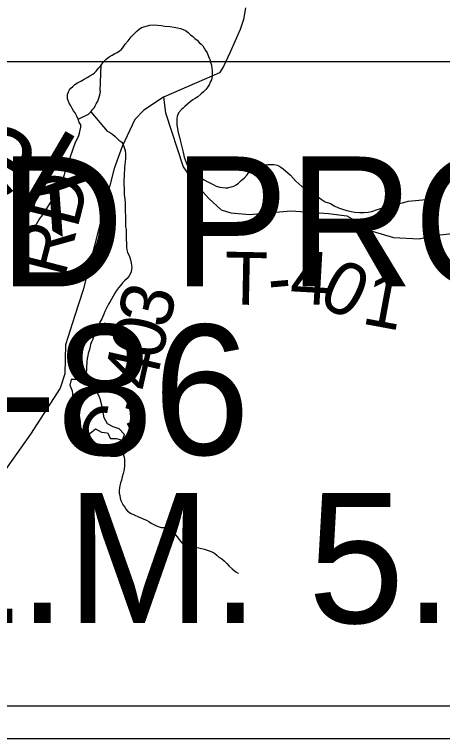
# Model space of a CAD drawing. Extents: x -59 to 82, y -3 to 49.
# Drawn here: x -51.129 to -50.668, y 42.491 to 43.271 of the extents above; entities that cross this region are included whole.
import ezdxf

# ---------------------------------------------------------------- set-up
doc = ezdxf.new("R2010")
doc.units = 0
for name, color, linetype in [('GM_X_Corporation', 7, 'Continuous'), ('GM_X_County_Road', 7, 'Continuous'), ('GM_X_County_Road_Text', 7, 'Continuous'), ('GM_X_Minor_Lake', 7, 'Continuous'), ('GM_X_Minor_River', 7, 'Continuous'), ('GM_X_Minor_River_Text', 7, 'Continuous'), ('GM_X_Township_Road', 7, 'Continuous'), ('GM_X_Township_Road_Text', 7, 'Continuous'), ('SH_Data', 7, 'Continuous')]:
    doc.layers.add(name, color=color, linetype=linetype)

msp = doc.modelspace()

# ---------------------------------------------------------------- linework, layer by layer
at = {"layer": 'GM_X_Corporation'}
for q in [(-48.09799, 42.49125), (-49.94786, 42.49125)]:
    msp.add_line((-54.89799, 42.49125), q, dxfattribs=at)
at = {"layer": 'GM_X_County_Road'}
for p, q in [((-50.88002, 43.27801), (-50.88211, 43.26547)), ((-50.88211, 43.26547), (-50.88559, 43.25479)), ((-50.88559, 43.25479), (-50.89627, 43.23017)), ((-50.89627, 43.23017), (-50.90346, 43.21485)), ((-50.90806, 43.20822), (-50.93272, 43.19743)), ((-50.90346, 43.21485), (-50.90806, 43.20822)), ((-50.93272, 43.19743), (-50.96824, 43.18176)), ((-50.96824, 43.18176), (-50.98953, 43.16783)), ((-50.98953, 43.16783), (-50.99899, 43.15765)), ((-50.99899, 43.15765), (-51.01281, 43.1289)), ((-51.01281, 43.1289), (-51.02123, 43.10517)), ((-51.02123, 43.10517), (-51.05474, 42.97432)), ((-51.05474, 42.97432), (-51.06363, 42.94692)), ((-51.06363, 42.94692), (-51.07363, 42.91533)), ((-51.07363, 42.91533), (-51.07453, 42.88382)), ((-51.07453, 42.88382), (-51.07935, 42.86859)), ((-51.07935, 42.86859), (-51.11156, 42.81901)), ((-51.11156, 42.81901), (-51.34477, 42.49125))]:
    msp.add_line(p, q, dxfattribs=at)
at = {"layer": 'GM_X_Minor_Lake'}
for p, q in [((-51.06764, 42.87779), (-51.06897, 42.87172)), ((-51.04694, 42.87782), (-51.06764, 42.87779)), ((-51.04247, 42.87024), (-51.04694, 42.87782)), ((-51.06897, 42.87172), (-51.06669, 42.86565)), ((-51.06669, 42.86565), (-51.06592, 42.85883)), ((-51.03987, 42.86534), (-51.04247, 42.87024)), ((-51.03639, 42.85698), (-51.03987, 42.86534)), ((-51.06592, 42.85883), (-51.06704, 42.852)), ((-51.06704, 42.852), (-51.06513, 42.84517)), ((-51.03448, 42.85015), (-51.03639, 42.85698)), ((-51.03218, 42.8365), (-51.03448, 42.85015)), ((-51.06513, 42.84517), (-51.05906, 42.83911)), ((-51.05906, 42.83911), (-51.05791, 42.83267)), ((-51.02838, 42.83006), (-51.03218, 42.8365)), ((-51.05791, 42.83267), (-51.05752, 42.82622)), ((-51.05752, 42.82622), (-51.0541, 42.82016)), ((-51.02232, 42.82704), (-51.02838, 42.83006)), ((-51.01588, 42.82477), (-51.02232, 42.82704)), ((-51.0541, 42.82016), (-51.04766, 42.81979)), ((-51.04766, 42.81979), (-51.04162, 42.82473)), ((-51.04162, 42.82473), (-51.03518, 42.82095)), ((-51.03518, 42.82095), (-51.02836, 42.82058)), ((-51.02836, 42.82058), (-51.02532, 42.81413)), ((-51.01018, 42.81871), (-51.01588, 42.82477)), ((-51.01244, 42.81264), (-51.01018, 42.81871)), ((-51.02532, 42.81413), (-51.01926, 42.81415)), ((-51.01926, 42.81415), (-51.01244, 42.81264))]:
    msp.add_line(p, q, dxfattribs=at)
at = {"layer": 'GM_X_Minor_River'}
for p, q in [((-50.99703, 43.25287), (-50.99439, 43.25517)), ((-50.99439, 43.25517), (-50.99175, 43.25671)), ((-50.99175, 43.25671), (-50.98304, 43.25944)), ((-50.98304, 43.25944), (-50.97886, 43.25985)), ((-50.97886, 43.25985), (-50.97468, 43.25949)), ((-50.97468, 43.25949), (-50.97088, 43.25914)), ((-50.97088, 43.25914), (-50.9667, 43.25841)), ((-50.9667, 43.25841), (-50.96138, 43.25807)), ((-50.96138, 43.25807), (-50.95682, 43.25734)), ((-50.95682, 43.25734), (-50.95301, 43.25661)), ((-50.95301, 43.25661), (-50.94997, 43.25587)), ((-50.94997, 43.25587), (-50.94692, 43.25475)), ((-51.00306, 43.24675), (-51.00004, 43.24981)), ((-51.00004, 43.24981), (-50.99703, 43.25287)), ((-50.94692, 43.25475), (-50.94464, 43.25362)), ((-50.94464, 43.25362), (-50.94158, 43.25136)), ((-50.94158, 43.25136), (-50.93928, 43.2491)), ((-50.93928, 43.2491), (-50.93661, 43.24722)), ((-50.93661, 43.24722), (-50.93431, 43.24495)), ((-51.00945, 43.23909), (-51.00644, 43.24254)), ((-51.00644, 43.24254), (-51.00306, 43.24675)), ((-50.93431, 43.24495), (-50.93202, 43.24307)), ((-50.93202, 43.24307), (-50.92972, 43.2408)), ((-50.92972, 43.2408), (-50.92781, 43.23891)), ((-51.01811, 43.22991), (-51.01547, 43.23183)), ((-51.01547, 43.23183), (-51.01358, 43.23336)), ((-51.01358, 43.23336), (-51.0117, 43.23566)), ((-51.0117, 43.23566), (-51.00945, 43.23909)), ((-50.92781, 43.23891), (-50.9259, 43.23702)), ((-50.9259, 43.23702), (-50.92436, 43.23475)), ((-50.92436, 43.23475), (-50.92282, 43.2321)), ((-50.92282, 43.2321), (-50.92128, 43.22945)), ((-51.02982, 43.2226), (-51.02681, 43.22528)), ((-51.02681, 43.22528), (-51.0234, 43.22721)), ((-51.0234, 43.22721), (-51.02076, 43.22875)), ((-51.02076, 43.22875), (-51.01811, 43.22991)), ((-50.92128, 43.22945), (-50.91973, 43.22566)), ((-50.91973, 43.22566), (-50.91818, 43.22225)), ((-51.0381, 43.21303), (-51.03547, 43.21647)), ((-51.03638, 43.18871), (-51.03547, 43.21647)), ((-51.03547, 43.21647), (-51.03284, 43.21992)), ((-51.03284, 43.21992), (-51.02982, 43.2226)), ((-50.91818, 43.22225), (-50.91739, 43.21845)), ((-50.91739, 43.21845), (-50.91661, 43.21617)), ((-50.91661, 43.21617), (-50.91621, 43.21276)), ((-51.04261, 43.20806), (-51.04073, 43.20997)), ((-51.04073, 43.20997), (-51.0381, 43.21303)), ((-50.91621, 43.21276), (-50.91581, 43.21048)), ((-50.91581, 43.21048), (-50.91579, 43.20743)), ((-51.05735, 43.19921), (-51.05357, 43.20113)), ((-51.05357, 43.20113), (-51.05055, 43.20306)), ((-51.05055, 43.20306), (-51.04753, 43.20498)), ((-51.04753, 43.20498), (-51.0445, 43.20652)), ((-51.0445, 43.20652), (-51.04261, 43.20806)), ((-50.91649, 43.20059), (-50.91761, 43.19868)), ((-50.91612, 43.20249), (-50.91649, 43.20059)), ((-50.91576, 43.20477), (-50.91612, 43.20249)), ((-50.91579, 43.20743), (-50.91576, 43.20477)), ((-51.06792, 43.19153), (-51.06604, 43.19344)), ((-51.06604, 43.19344), (-51.06378, 43.19536)), ((-51.06378, 43.19536), (-51.06075, 43.19728)), ((-51.06075, 43.19728), (-51.05735, 43.19921)), ((-50.9206, 43.19295), (-50.92248, 43.19027)), ((-50.9191, 43.19524), (-50.9206, 43.19295)), ((-50.91761, 43.19868), (-50.9191, 43.19524)), ((-51.07166, 43.18389), (-51.07129, 43.1858)), ((-51.07129, 43.1858), (-51.07055, 43.1877)), ((-51.07055, 43.1877), (-51.06943, 43.18961)), ((-51.06943, 43.18961), (-51.06792, 43.19153)), ((-51.0371, 43.18338), (-51.03636, 43.18567)), ((-51.036, 43.18833), (-51.03638, 43.18871)), ((-51.03636, 43.18567), (-51.036, 43.18833)), ((-50.92813, 43.18491), (-50.93115, 43.18223)), ((-50.92512, 43.18759), (-50.92813, 43.18491)), ((-50.92248, 43.19027), (-50.92512, 43.18759)), ((-51.07163, 43.18009), (-51.07166, 43.18389)), ((-51.07085, 43.1782), (-51.07163, 43.18009)), ((-51.06969, 43.17554), (-51.07085, 43.1782)), ((-51.04083, 43.17461), (-51.03895, 43.17766)), ((-51.03895, 43.17766), (-51.03784, 43.18071)), ((-51.03784, 43.18071), (-51.0371, 43.18338)), ((-50.93644, 43.17915), (-50.93946, 43.17684)), ((-50.93417, 43.18031), (-50.93644, 43.17915)), ((-50.93115, 43.18223), (-50.93417, 43.18031)), ((-51.06815, 43.17251), (-51.06969, 43.17554)), ((-51.06661, 43.16948), (-51.06815, 43.17251)), ((-51.06507, 43.16721), (-51.06661, 43.16948)), ((-51.0442, 43.16888), (-51.04269, 43.17079)), ((-51.04269, 43.17079), (-51.04195, 43.1727)), ((-51.04195, 43.1727), (-51.04083, 43.17461)), ((-50.947, 43.16995), (-50.94888, 43.16841)), ((-50.94511, 43.17186), (-50.947, 43.16995)), ((-50.94247, 43.17416), (-50.94511, 43.17186)), ((-50.93946, 43.17684), (-50.94247, 43.17416)), ((-51.06353, 43.16494), (-51.06507, 43.16721)), ((-51.0616, 43.16153), (-51.06353, 43.16494)), ((-51.06006, 43.15812), (-51.0616, 43.16153)), ((-51.06006, 43.15812), (-51.04909, 43.16352)), ((-51.04909, 43.16352), (-51.04645, 43.1662)), ((-51.04645, 43.1662), (-51.0442, 43.16888)), ((-51.04645, 43.1662), (-51.02882, 43.14541)), ((-50.95189, 43.16497), (-50.95338, 43.16116)), ((-50.94888, 43.16841), (-50.95189, 43.16497)), ((-51.05889, 43.1547), (-51.06006, 43.15812)), ((-51.05735, 43.15205), (-51.05889, 43.1547)), ((-50.95338, 43.16116), (-50.95374, 43.15887)), ((-50.95374, 43.15887), (-50.95372, 43.15583)), ((-50.95372, 43.15583), (-50.95368, 43.15165)), ((-51.05843, 43.14482), (-51.05733, 43.14939)), ((-51.05733, 43.14939), (-51.05735, 43.15205)), ((-50.95368, 43.15165), (-50.95328, 43.14823)), ((-50.95328, 43.14823), (-50.95288, 43.14557)), ((-51.06178, 43.13567), (-51.06065, 43.13796)), ((-51.06065, 43.13796), (-51.05954, 43.14063)), ((-51.05954, 43.14063), (-51.0588, 43.14292)), ((-51.0588, 43.14292), (-51.05843, 43.14482)), ((-51.02882, 43.14541), (-51.02653, 43.14428)), ((-51.02653, 43.14428), (-51.0231, 43.14203)), ((-51.0231, 43.14203), (-51.02042, 43.13939)), ((-51.02042, 43.13939), (-51.01851, 43.13788)), ((-50.95288, 43.14557), (-50.95209, 43.14253)), ((-50.95209, 43.14253), (-50.95092, 43.13874)), ((-50.95092, 43.13874), (-50.94975, 43.13418)), ((-51.06475, 43.12842), (-51.06327, 43.13224)), ((-51.06327, 43.13224), (-51.06178, 43.13567)), ((-51.01851, 43.13788), (-51.01621, 43.13561)), ((-51.01621, 43.13561), (-51.01315, 43.13335)), ((-51.01315, 43.13335), (-51.012, 43.13146)), ((-51.012, 43.13146), (-51.01084, 43.12881)), ((-50.94975, 43.13418), (-50.94856, 43.12849)), ((-51.06809, 43.11889), (-51.06624, 43.12423)), ((-51.06624, 43.12423), (-51.06475, 43.12842)), ((-51.01084, 43.12881), (-51.01006, 43.12653)), ((-51.01006, 43.12653), (-51.00966, 43.12425)), ((-51.00966, 43.12425), (-51.00925, 43.12083)), ((-50.94856, 43.12849), (-50.947, 43.1228)), ((-50.947, 43.1228), (-50.94581, 43.1171)), ((-51.06957, 43.11356), (-51.06809, 43.11889)), ((-51.00921, 43.11551), (-51.00957, 43.11246)), ((-51.00925, 43.12083), (-51.00923, 43.11817)), ((-51.00923, 43.11817), (-51.00921, 43.11551)), ((-50.94581, 43.1171), (-50.94426, 43.11255)), ((-51.07366, 43.10212), (-51.07143, 43.10822)), ((-51.07143, 43.10822), (-51.06957, 43.11356)), ((-51.00992, 43.10904), (-51.01027, 43.10599)), ((-51.00957, 43.11246), (-51.00992, 43.10904)), ((-50.94426, 43.11255), (-50.94271, 43.10876)), ((-50.94271, 43.10876), (-50.94116, 43.10573)), ((-50.86864, 43.10548), (-50.86447, 43.10703)), ((-50.86447, 43.10703), (-50.85993, 43.10858)), ((-50.85993, 43.10858), (-50.85576, 43.10937)), ((-50.85576, 43.10937), (-50.85196, 43.1094)), ((-50.85196, 43.1094), (-50.84892, 43.10942)), ((-50.84892, 43.10942), (-50.84588, 43.10868)), ((-50.84588, 43.10868), (-50.84397, 43.10794)), ((-50.84397, 43.10794), (-50.84168, 43.10643)), ((-51.07551, 43.0964), (-51.07366, 43.10212)), ((-51.01025, 43.10333), (-51.01061, 43.10029)), ((-51.01061, 43.10029), (-51.01058, 43.09649)), ((-51.01027, 43.10599), (-51.01025, 43.10333)), ((-50.94116, 43.10573), (-50.93849, 43.10346)), ((-50.93849, 43.10346), (-50.93619, 43.10158)), ((-50.93619, 43.10158), (-50.93313, 43.09894)), ((-50.87807, 43.09819), (-50.87469, 43.10277)), ((-50.87469, 43.10277), (-50.86864, 43.10548)), ((-50.84168, 43.10643), (-50.83939, 43.10455)), ((-50.83939, 43.10455), (-50.83136, 43.09776)), ((-51.08112, 43.08572), (-51.07775, 43.09145)), ((-51.07775, 43.09145), (-51.07551, 43.0964)), ((-51.01058, 43.09649), (-51.01093, 43.09268)), ((-51.01093, 43.09268), (-51.01091, 43.0904)), ((-50.93313, 43.09894), (-50.93046, 43.09667)), ((-50.93046, 43.09667), (-50.9274, 43.0948)), ((-50.9274, 43.0948), (-50.92435, 43.09292)), ((-50.92435, 43.09292), (-50.9213, 43.09104)), ((-50.88749, 43.08938), (-50.88447, 43.09206)), ((-50.88447, 43.09206), (-50.88108, 43.09512)), ((-50.88108, 43.09512), (-50.87807, 43.09819)), ((-50.83136, 43.09776), (-50.82868, 43.09474)), ((-50.82868, 43.09474), (-50.82561, 43.09134)), ((-50.82561, 43.09134), (-50.82255, 43.08869)), ((-51.08372, 43.07847), (-51.08112, 43.08572)), ((-51.01091, 43.0904), (-51.01045, 43.08128)), ((-50.9213, 43.09104), (-50.91672, 43.08879)), ((-50.91672, 43.08879), (-50.91405, 43.08728)), ((-50.91405, 43.08728), (-50.91139, 43.08616)), ((-50.91139, 43.08616), (-50.90758, 43.08505)), ((-50.90758, 43.08505), (-50.90454, 43.08469)), ((-50.90454, 43.08469), (-50.9015, 43.08433)), ((-50.9015, 43.08433), (-50.89884, 43.08435)), ((-50.89884, 43.08435), (-50.89543, 43.08514)), ((-50.89543, 43.08514), (-50.8924, 43.08592)), ((-50.8924, 43.08592), (-50.88976, 43.08746)), ((-50.88976, 43.08746), (-50.88749, 43.08938)), ((-50.82255, 43.08869), (-50.81911, 43.08568)), ((-50.81911, 43.08568), (-50.8153, 43.08342)), ((-50.8153, 43.08342), (-50.8111, 43.08079)), ((-50.67401, 43.07948), (-50.67063, 43.08445)), ((-50.67063, 43.08445), (-50.66914, 43.08712)), ((-50.66914, 43.08712), (-50.66727, 43.09056)), ((-51.08596, 43.07389), (-51.08372, 43.07847)), ((-51.01045, 43.08128), (-51.01042, 43.07709)), ((-51.01042, 43.07709), (-51.01, 43.07215)), ((-50.8111, 43.08079), (-50.8069, 43.07778)), ((-50.8069, 43.07778), (-50.8027, 43.07515)), ((-50.68004, 43.07411), (-50.67588, 43.07566)), ((-50.67588, 43.07566), (-50.67398, 43.07568)), ((-50.67398, 43.07568), (-50.67401, 43.07948)), ((-51.09196, 43.06473), (-51.08896, 43.06969)), ((-51.08896, 43.06969), (-51.08596, 43.07389)), ((-51.01, 43.07215), (-51.00959, 43.06797)), ((-51.00959, 43.06797), (-51.00956, 43.06417)), ((-50.8027, 43.07515), (-50.7985, 43.07213)), ((-50.7985, 43.07213), (-50.79392, 43.06912)), ((-50.79392, 43.06912), (-50.78821, 43.06726)), ((-50.71644, 43.06701), (-50.71303, 43.0678)), ((-50.71303, 43.0678), (-50.70924, 43.06858)), ((-50.70924, 43.06858), (-50.70469, 43.06976)), ((-50.70469, 43.06976), (-50.70052, 43.07017)), ((-50.70052, 43.07017), (-50.69672, 43.07057)), ((-50.69672, 43.07057), (-50.69331, 43.07098)), ((-50.69331, 43.07098), (-50.68913, 43.07139)), ((-50.68913, 43.07139), (-50.68648, 43.07179)), ((-50.68648, 43.07179), (-50.68383, 43.07256)), ((-50.68383, 43.07256), (-50.68004, 43.07411)), ((-51.09834, 43.05517), (-51.09496, 43.06014)), ((-51.09496, 43.06014), (-51.09196, 43.06473)), ((-51.00956, 43.06417), (-51.00953, 43.06037)), ((-51.00953, 43.06037), (-51.00951, 43.05771)), ((-50.78821, 43.06726), (-50.78439, 43.06501)), ((-50.78439, 43.06501), (-50.77982, 43.06276)), ((-50.77982, 43.06276), (-50.77525, 43.06127)), ((-50.77525, 43.06127), (-50.77068, 43.05978)), ((-50.74371, 43.05883), (-50.73765, 43.06078)), ((-50.73765, 43.06078), (-50.73235, 43.06272)), ((-50.73235, 43.06272), (-50.72743, 43.06465)), ((-50.72743, 43.06465), (-50.72326, 43.06582)), ((-50.72326, 43.06582), (-50.71985, 43.06661)), ((-50.71985, 43.06661), (-50.71644, 43.06701)), ((-51.1021, 43.0502), (-51.09834, 43.05517)), ((-51.00951, 43.05771), (-51.0091, 43.05467)), ((-51.0091, 43.05467), (-51.00906, 43.04973)), ((-50.77068, 43.05978), (-50.76611, 43.05867)), ((-50.76611, 43.05867), (-50.76193, 43.05794)), ((-50.76193, 43.05794), (-50.75699, 43.0576)), ((-50.75699, 43.0576), (-50.75243, 43.05763)), ((-50.75243, 43.05763), (-50.74788, 43.05804)), ((-50.74788, 43.05804), (-50.74371, 43.05883)), ((-51.10772, 43.0418), (-51.10509, 43.04524)), ((-51.10509, 43.04524), (-51.1021, 43.0502)), ((-51.00906, 43.04973), (-51.00903, 43.0463)), ((-51.00903, 43.0463), (-51.00901, 43.04402)), ((-51.11336, 43.03529), (-51.11073, 43.03835)), ((-51.11073, 43.03835), (-51.10772, 43.0418)), ((-51.00901, 43.04402), (-51.009, 43.04212)), ((-51.009, 43.04212), (-51.0086, 43.03946)), ((-51.0086, 43.03946), (-51.00858, 43.0368)), ((-51.00858, 43.0368), (-51.00855, 43.03376)), ((-51.12203, 43.02725), (-51.11977, 43.02954)), ((-51.11977, 43.02954), (-51.11714, 43.03223)), ((-51.11714, 43.03223), (-51.11336, 43.03529)), ((-51.00855, 43.03376), (-51.00853, 43.0311)), ((-51.00853, 43.0311), (-51.00851, 43.02806)), ((-51.1292, 43.02073), (-51.12656, 43.02303)), ((-51.12656, 43.02303), (-51.1243, 43.02533)), ((-51.1243, 43.02533), (-51.12203, 43.02725)), ((-51.00851, 43.02806), (-51.0081, 43.02502)), ((-51.0081, 43.02502), (-51.00808, 43.02312)), ((-51.00808, 43.02312), (-51.00806, 43.02045)), ((-51.00806, 43.02045), (-51.00766, 43.01741)), ((-51.00766, 43.01741), (-51.00688, 43.01476)), ((-51.00688, 43.01476), (-51.00572, 43.0121)), ((-51.00572, 43.0121), (-51.00494, 43.01021)), ((-51.00494, 43.01021), (-51.00378, 43.00679)), ((-51.00378, 43.00679), (-51.00299, 43.00338)), ((-51.00299, 43.00338), (-51.00259, 43.00072)), ((-51.00259, 43.00072), (-51.00219, 42.99844)), ((-51.00219, 42.99844), (-51.00255, 42.99616)), ((-51.00366, 42.99197), (-51.00515, 42.98929)), ((-51.00291, 42.99387), (-51.00366, 42.99197)), ((-51.00255, 42.99616), (-51.00291, 42.99387)), ((-51.01231, 42.98202), (-51.01419, 42.97934)), ((-51.01005, 42.98394), (-51.01231, 42.98202)), ((-51.00741, 42.98662), (-51.01005, 42.98394)), ((-51.00515, 42.98929), (-51.00741, 42.98662)), ((-51.01682, 42.97666), (-51.0187, 42.97361)), ((-51.01419, 42.97934), (-51.01682, 42.97666)), ((-51.02244, 42.9675), (-51.02432, 42.96444)), ((-51.02057, 42.97093), (-51.02244, 42.9675)), ((-51.0187, 42.97361), (-51.02057, 42.97093)), ((-51.02731, 42.9591), (-51.03143, 42.95108)), ((-51.02582, 42.96177), (-51.02731, 42.9591)), ((-51.02432, 42.96444), (-51.02582, 42.96177)), ((-51.03143, 42.95108), (-51.03254, 42.94803)), ((-51.03478, 42.94307), (-51.03665, 42.93964)), ((-51.03254, 42.94803), (-51.03478, 42.94307)), ((-51.03814, 42.9362), (-51.04001, 42.93277)), ((-51.03665, 42.93964), (-51.03814, 42.9362)), ((-51.0415, 42.92896), (-51.04299, 42.92591)), ((-51.04001, 42.93277), (-51.0415, 42.92896)), ((-51.04485, 42.92019), (-51.04596, 42.91752)), ((-51.04411, 42.92285), (-51.04485, 42.92019)), ((-51.04299, 42.92591), (-51.04411, 42.92285)), ((-51.04707, 42.91333), (-51.0478, 42.91028)), ((-51.04671, 42.91561), (-51.04707, 42.91333)), ((-51.04596, 42.91752), (-51.04671, 42.91561)), ((-51.04928, 42.90571), (-51.04965, 42.9038)), ((-51.04854, 42.90799), (-51.04928, 42.90571)), ((-51.0478, 42.91028), (-51.04854, 42.90799)), ((-51.05038, 42.90038), (-51.05073, 42.89695)), ((-51.05073, 42.89695), (-51.05072, 42.89505)), ((-51.04965, 42.9038), (-51.05038, 42.90038)), ((-51.05106, 42.8901), (-51.05182, 42.87781)), ((-51.05072, 42.89505), (-51.05108, 42.89239)), ((-51.05108, 42.89239), (-51.05106, 42.8901)), ((-51.01396, 42.81298), (-51.01275, 42.80179)), ((-51.01275, 42.80179), (-51.01159, 42.79952)), ((-51.01159, 42.79952), (-51.01119, 42.79648)), ((-51.01119, 42.79648), (-51.01041, 42.7942)), ((-51.01041, 42.7942), (-51.01039, 42.79154)), ((-51.01039, 42.79154), (-51.01037, 42.78888)), ((-51.01037, 42.78888), (-51.01034, 42.78507)), ((-51.01068, 42.78089), (-51.01179, 42.7767)), ((-51.01034, 42.78507), (-51.01068, 42.78089)), ((-51.0129, 42.77289), (-51.01363, 42.76946)), ((-51.01179, 42.7767), (-51.0129, 42.77289)), ((-51.01436, 42.76642), (-51.0151, 42.76337)), ((-51.01363, 42.76946), (-51.01436, 42.76642)), ((-51.01546, 42.76109), (-51.01582, 42.7588)), ((-51.01582, 42.7588), (-51.01579, 42.75538)), ((-51.0151, 42.76337), (-51.01546, 42.76109)), ((-51.01579, 42.75538), (-51.0154, 42.7531)), ((-51.0154, 42.7531), (-51.01499, 42.75006)), ((-51.01499, 42.75006), (-51.01421, 42.74741)), ((-51.01421, 42.74741), (-51.01267, 42.74476)), ((-51.01267, 42.74476), (-51.01151, 42.74249)), ((-51.01151, 42.74249), (-51.00997, 42.74021)), ((-51.00997, 42.74021), (-51.00844, 42.73794)), ((-51.00844, 42.73794), (-51.0069, 42.73605)), ((-51.0069, 42.73605), (-51.00308, 42.73342)), ((-51.00308, 42.73342), (-51.00042, 42.7323)), ((-51.00042, 42.7323), (-50.99432, 42.72968)), ((-50.99432, 42.72968), (-50.99165, 42.72856)), ((-50.99165, 42.72856), (-50.98937, 42.72743)), ((-50.98937, 42.72743), (-50.9867, 42.72631)), ((-50.9867, 42.72631), (-50.98403, 42.72481)), ((-50.98403, 42.72481), (-50.98136, 42.72331)), ((-50.98136, 42.72331), (-50.97869, 42.72181)), ((-50.97869, 42.72181), (-50.97564, 42.72031)), ((-50.97564, 42.72031), (-50.97297, 42.71919)), ((-50.97297, 42.71919), (-50.97069, 42.71844)), ((-50.97069, 42.71844), (-50.96879, 42.71845)), ((-50.96879, 42.71845), (-50.96689, 42.71847)), ((-50.96689, 42.71847), (-50.96423, 42.71849)), ((-50.96423, 42.71849), (-50.96157, 42.71737)), ((-50.96157, 42.71737), (-50.95889, 42.71473)), ((-50.95889, 42.71473), (-50.95697, 42.71284)), ((-50.95697, 42.71284), (-50.95544, 42.71057)), ((-50.95544, 42.71057), (-50.95352, 42.7083)), ((-50.95352, 42.7083), (-50.9516, 42.70603)), ((-50.9516, 42.70603), (-50.95007, 42.70376)), ((-50.95007, 42.70376), (-50.94853, 42.70187)), ((-50.94853, 42.70187), (-50.94586, 42.69961)), ((-50.94586, 42.69961), (-50.94281, 42.69849)), ((-50.94281, 42.69849), (-50.94053, 42.69813)), ((-50.94053, 42.69813), (-50.93749, 42.69777)), ((-50.93749, 42.69777), (-50.93558, 42.6974)), ((-50.93558, 42.6974), (-50.93292, 42.69704)), ((-50.93292, 42.69704), (-50.93026, 42.69668)), ((-50.93026, 42.69668), (-50.92722, 42.69594)), ((-50.92722, 42.69594), (-50.92418, 42.6952)), ((-50.92418, 42.6952), (-50.92113, 42.69408)), ((-50.92113, 42.69408), (-50.91808, 42.69296)), ((-50.91808, 42.69296), (-50.91542, 42.69184)), ((-50.91542, 42.69184), (-50.91313, 42.69072)), ((-50.91313, 42.69072), (-50.91083, 42.68883)), ((-50.91083, 42.68883), (-50.90854, 42.68657)), ((-50.90854, 42.68657), (-50.90548, 42.68469)), ((-50.90548, 42.68469), (-50.90281, 42.68243)), ((-50.90281, 42.68243), (-50.90013, 42.67978)), ((-50.90013, 42.67978), (-50.89745, 42.67676)), ((-50.89745, 42.67676), (-50.89439, 42.67412)), ((-50.89439, 42.67412), (-50.89209, 42.67224)), ((-50.89209, 42.67224), (-50.89018, 42.67073)), ((-50.89018, 42.67073), (-50.88789, 42.66923)), ((-50.88789, 42.66923), (-50.88789, 42.66923)), ((-50.88789, 42.66923), (-50.88751, 42.66885))]:
    msp.add_line(p, q, dxfattribs=at)
at = {"layer": 'GM_X_Township_Road'}
for p, q in [((-50.96824, 43.18176), (-50.96588, 43.16513)), ((-50.96588, 43.16513), (-50.94698, 43.10671)), ((-50.94698, 43.10671), (-50.93679, 43.0918)), ((-50.93679, 43.0918), (-50.91933, 43.07287)), ((-50.91933, 43.07287), (-50.90624, 43.06051)), ((-50.90624, 43.06051), (-50.8957, 43.05723)), ((-50.8957, 43.05723), (-50.87569, 43.05541)), ((-50.87569, 43.05541), (-50.85569, 43.05723)), ((-50.85569, 43.05723), (-50.83059, 43.05942)), ((-50.83059, 43.05942), (-50.79058, 43.05651)), ((-50.79058, 43.05651), (-50.77058, 43.05396)), ((-50.77058, 43.05396), (-50.7593, 43.04777)), ((-50.7593, 43.04777), (-50.7433, 43.03759)), ((-50.7433, 43.03759), (-50.72038, 43.03067)), ((-50.72038, 43.03067), (-50.69275, 43.02922)), ((-50.69275, 43.02922), (-50.67711, 43.03285)), ((-50.67711, 43.03285), (-50.65681, 43.03492))]:
    msp.add_line(p, q, dxfattribs=at)
at = {"layer": 'SH_Data'}
msp.add_line((-54.89799, 42.49125), (-48.09799, 42.49125), dxfattribs=at)
msp.add_lwpolyline([(-51.47834, 42.52649), (-49.7208, 42.52649), (-49.7208, 43.21994), (-51.47834, 43.21994)], close=True, dxfattribs=at)
msp.add_lwpolyline([(-51.47834, 42.52649), (-49.7208, 42.52649), (-49.7208, 43.21994), (-51.47834, 43.21994)], close=True, dxfattribs=at)

# ---------------------------------------------------------------- texts
at = {"layer": 'GM_X_County_Road_Text'}
for s, height, rotation, p in [('RD', 0.056818, 75.60477, (-51.07482, 42.98596)), ('3', 0.05682, 76.36763, (-50.96324, 42.93128)), ('0', 0.05682, 77.50011, (-50.97075, 42.8974)), ('4', 0.05682, 77.4222, (-50.97839, 42.86316)), ('-', 0.05682, 73.4474, (-50.98613, 42.83662)), ('C', 0.05682, 57.95448, (-51.01777, 42.78182))]:
    msp.add_text(s, height=height, rotation=rotation, dxfattribs=at).set_placement(p)
at = {"layer": 'GM_X_Minor_River_Text'}
msp.add_text('Creek', height=0.094776, rotation=329.63598, dxfattribs=at).set_placement((-51.3686, 43.20234))
at = {"layer": 'GM_X_Township_Road_Text'}
for s, rotation, p in [('T', 358.86855, (-50.90292, 42.95875)), ('4', 356.83951, (-50.83285, 42.96004)), ('0', 333.24643, (-50.80384, 42.9597)), ('1', 349.48887, (-50.756, 42.93835)), ('-', 4.80533, (-50.85402, 42.95812))]:
    msp.add_text(s, height=0.05682, rotation=rotation, dxfattribs=at).set_placement(p)
at = {"layer": 'SH_Data'}
for s, p in [('END PROJECT', (-51.4057, 42.97799)), ('SR-86', (-51.4057, 42.7968)), ('S.L.M. 5.54', (-51.4057, 42.61561))]:
    msp.add_text(s, height=0.14, dxfattribs=at).set_placement(p)

doc.saveas('drawing.dxf')
